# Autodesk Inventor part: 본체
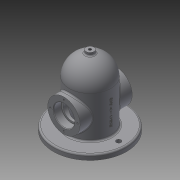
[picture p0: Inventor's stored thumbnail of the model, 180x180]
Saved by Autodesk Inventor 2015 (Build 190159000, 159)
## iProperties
Created: 2019-11
Part Number: 본체
Material: 일반
Document SubType Name: Modeling
Designer: now
Density: 1 g/cm^3
Appearance: 기본값
Author: now
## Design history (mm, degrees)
sketch "스케치1"
  geometry: C1 r 70 at (0, 0); 1 further point
  constraints: 1 centre point, 1 coincident
  dimensions: "d0" = 140 diameter of C1
extrude "돌출1" new body sketch "스케치1" distance "d1" = 10; taper "d2" = 0 deg
sketch "스케치2"
  geometry: C1 r 70 at (0, 0) reference; C2 r 40 at (0, 0)
  constraints: 1 centre point, 1 coincident
  dimensions: "d3" = 80 diameter of C2
extrude "돌출2" join sketch "스케치2" distance "d4" = 120; taper "d5" = 0 deg
fillet "모깎기1" dims "d6" = 40
feature "쉘1" dims "d7" = 10
node "작업 평면1"
sketch "스케치4"
  geometry: L1 (-70, 0)-(70, 0) reference; C1 r 31 at (0, 50); 1 further point
  constraints: 1 centre point, 1 vertical alignment
  dimensions: "d9" = 62 diameter of C1; "d10" = 50 distance from line of L1 C1.centre
extrude "돌출3" join sketch "스케치4" stored distance "d11" = 120; taper "d12" = 0 deg
sketch "스케치5"
  geometry: C1 r 31 at (0, 0) reference; 1 further point
hole "구멍1" sketch "스케치5" at (0, 0) diameter "d13" = 40; stored, may be unused: countersink angle "d17" = 90 deg, drill point angle "d19" = 0 deg; dims "d14" = 6, "d15" = 4, "d16" = 2, "d18" = 15
sketch "스케치6"
  geometry: C1 r 20 at (0, 0) reference; 1 further point
hole "구멍2" sketch "스케치6" at (0, 0) diameter "d20" = 33; stored, may be unused: countersink angle "d24" = 90 deg, drill point angle "d26" = 0 deg; dims "d21" = 6, "d22" = 4, "d23" = 2, "d25" = 35
node "작업 평면2"
sketch "스케치7"
  geometry: C1 r 7.5 at (0, 0); 1 further point
  constraints: 1 centre point, 1 coincident
  dimensions: "d28" = 15 diameter of C1
extrude "돌출4" join sketch "스케치7" stored distance "d29" = 120; taper "d30" = 0 deg
sketch "스케치8"
  geometry: C1 r 7.5 at (0, 0) reference
hole "구멍3" sketch "스케치8" at (0, 0) diameter "d31" = 5.188; stored, may be unused: countersink angle "d35" = 90 deg, drill point angle "d37" = 0 deg; dims "d32" = 12, "d33" = 4, "d34" = 2, "d36" = 40
sketch "스케치9"
  geometry: C1 r 20 at (0, 0) reference; 2 further points
  constraints: 1 vertical alignment
  dimensions: "d38" = 26 distance of C1.centre point (0, 26)
hole "구멍4" sketch "스케치9" at (0, 26) diameter "d39" = 3.242; stored, may be unused: countersink angle "d43" = 90 deg, drill point angle "d45" = 118 deg; dims "d40" = 8, "d41" = 4, "d42" = 2, "d44" = 10
fillet "모깎기2" dims "d49" = 0.3
sketch "스케치10"
  geometry: C1 r 40 at (0, 0) reference; 2 further points
  constraints: 2 horizontal alignment
  dimensions: "d50" = 55 distance of C1.centre point (-55, 0); "d51" = 55 distance of C1.centre point (55, 0)
hole "구멍5" sketch "스케치10" at (-55, 0), (55, 0) diameter "d52" = 9; stored, may be unused: countersink angle "d56" = 90 deg, drill point angle "d58" = 118 deg; dims "d53" = 8, "d54" = 4, "d55" = 2, "d57" = 10
fillet "모깎기3" dims "d59" = 3
chamfer "모따기1" distance "d60" = 1; stored, may be unused: second distance "d61" = 2, angle "d62" = 45 deg
node "작업 평면4"
sketch "스케치12"
  geometry: L1 (-70, 0)-(70, 0) reference; 2 further points
  constraints: 1 vertical alignment, 1 other
  dimensions: "d66" = 50 distance from line of L1 point (0, 50)
feature "엠보싱1" sketch "스케치12" dims "d67" = 0.5, "d68" = 0
fillet "모깎기4" dims "d69" = 3
node "솔리드1"
mirror "대칭1"
mirror "대칭2"
pattern_circular "원형 패턴1" dims angle "d47" = 360 deg
mirror "대칭3"
other parameters: "d27" = 135, "d65" = 40.5
